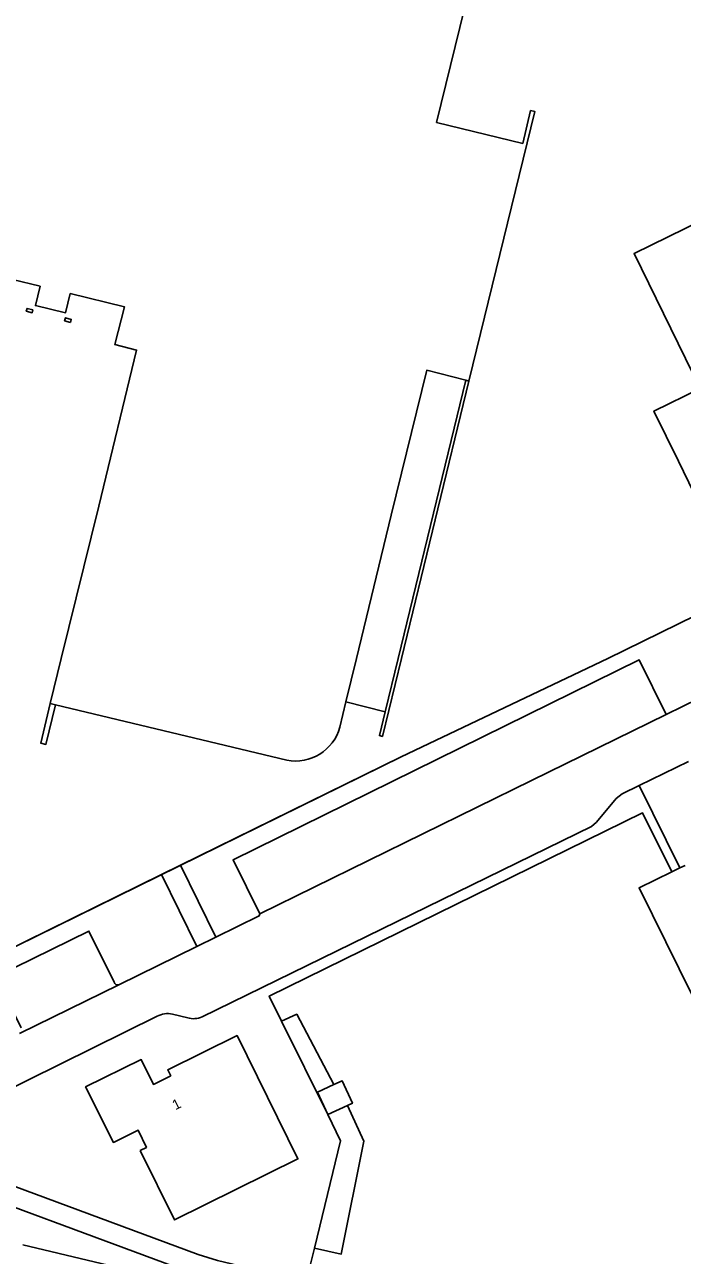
# Model space of a CAD drawing. Extents: x 163046 to 165074, y 382019 to 382874.
# Drawn here: x 163184.8 to 163250, y 382690.8 to 382812.9 of the extents above; entities that cross this region are included whole.
import ezdxf

# ---------------------------------------------------------------- set-up
doc = ezdxf.new("R2010")
doc.units = 0
for name, color, linetype in [('IMGEO_Fietspad_open', 7, 'Continuous'), ('IMGEO_Groenvoorziening', 7, 'Continuous'), ('IMGEO_Hek', 7, 'Continuous'), ('IMGEO_Muur', 7, 'Continuous'), ('IMGEO_Pand', 7, 'Continuous'), ('IMGEO_Pand_nummerreeks', 7, 'Continuous'), ('IMGEO_Parkeervlak_open', 7, 'Continuous'), ('IMGEO_Rijbaan_lokaal_gesloten', 7, 'Continuous'), ('IMGEO_Voetpad_open', 7, 'Continuous')]:
    doc.layers.add(name, color=color, linetype=linetype)

msp = doc.modelspace()

# ---------------------------------------------------------------- linework, layer by layer
at = {"layer": 'IMGEO_Fietspad_open'}
for points in [[(163172.35, 382701.93), (163176, 382700.52), (163201.96, 382690.91), (163203.88, 382690.32), (163252.46, 382678.73)], [(163252.01, 382676.83), (163203.95, 382688.31), (163202.36, 382688.7), (163201.62, 382688.96), (163172.54, 382699.75), (163171.68, 382699.94), (163168.8, 382700.21)]]:
    msp.add_lwpolyline(points, dxfattribs=at)
at = {"layer": 'IMGEO_Groenvoorziening'}
for points in [[(163200.21, 382729.51), (163222.08, 382740.26), (163242.58, 382750), (163320.84, 382788.38), (163326.4, 382790.68), (163329.21, 382791.76), (163334.82, 382793.72), (163337.67, 382794.6), (163343.5, 382795.94), (163349.43, 382797.09), (163352.45, 382797.4), (163359.37, 382797.83)], [(163163.24, 382720.72), (163175.88, 382717.55), (163198.33, 382728.59)]]:
    msp.add_lwpolyline(points, dxfattribs=at)
at = {"layer": 'IMGEO_Hek'}
for points in [[(163359.37, 382797.83), (163352.45, 382797.4), (163349.43, 382797.09), (163343.5, 382795.94), (163337.67, 382794.6), (163334.82, 382793.72), (163329.21, 382791.76), (163326.4, 382790.68), (163320.84, 382788.38), (163242.58, 382750), (163222.08, 382740.26)], [(163222.08, 382740.26), (163175.88, 382717.55), (163161.49, 382721.16)]]:
    msp.add_lwpolyline(points, dxfattribs=at)
at = {"layer": 'IMGEO_Muur'}
for points in [[(163228.81, 382777.5), (163222.11, 382750), (163220.23, 382742.28), (163219.93, 382742.36), (163220.5, 382744.72)], [(163220.5, 382744.72), (163221.79, 382750), (163228.51, 382777.59)], [(163187.82, 382745.42), (163186.87, 382741.49), (163186.35, 382741.62), (163187.29, 382745.55)]]:
    msp.add_lwpolyline(points, dxfattribs=at)
at = {"layer": 'IMGEO_Pand'}
for points in [[(163187.29, 382745.55), (163188.39, 382750), (163192.11, 382765.11), (163195.86, 382780.59), (163193.71, 382781.12), (163194.64, 382784.88), (163189.27, 382786.19), (163188.81, 382784.29), (163185.83, 382785), (163186.29, 382786.91), (163175.29, 382789.56), (163181.21, 382813.84), (163184.93, 382829.07), (163223.48, 382819.67), (163229.29, 382818.25), (163225.61, 382803.16), (163234.14, 382801.08), (163234.93, 382804.33), (163235.33, 382804.24), (163228.81, 382777.5)], [(163260.37, 382797.58), (163257.72, 382803.04), (163272.56, 382810.28), (163275.22, 382804.81), (163285.92, 382810.05), (163288.8, 382804.14), (163299.84, 382781.52), (163300.53, 382780.1), (163259.8, 382760.22), (163255.22, 382757.98), (163249.59, 382769.57), (163247.16, 382774.53), (163251.73, 382776.78), (163245.19, 382790.17), (163260.37, 382797.58)], [(163185.58, 382784.57), (163185.5, 382784.28), (163184.92, 382784.43), (163185, 382784.72), (163185.58, 382784.57)], [(163189.29, 382783.33), (163188.71, 382783.49), (163188.79, 382783.78), (163189.37, 382783.62), (163189.29, 382783.33)], [(163216.6, 382745.71), (163217.65, 382750), (163221.11, 382764.2), (163224.63, 382778.58), (163228.51, 382777.59)], [(163228.51, 382777.59), (163228.81, 382777.5)], [(163216.6, 382745.71), (163216.01, 382743.2)], [(163187.29, 382745.55), (163187.82, 382745.42)], [(163210.74, 382739.91), (163187.82, 382745.42)], [(163196.2, 382701.21), (163196.83, 382701.53), (163196.01, 382703.25), (163193.55, 382702.02), (163190.8, 382707.52), (163196.32, 382710.24), (163197.53, 382707.78), (163199.24, 382708.63), (163198.95, 382709.22), (163205.82, 382712.62), (163211.85, 382700.39), (163199.63, 382694.34), (163196.2, 382701.21)], [(163216.76, 382705.68), (163217.25, 382705.9), (163216.23, 382708.13), (163215.4, 382707.75)], [(163214.82, 382704.79), (163213.8, 382707.02), (163215.4, 382707.75)], [(163216.76, 382705.68), (163214.82, 382704.79)]]:
    msp.add_lwpolyline(points, dxfattribs=at)
msp.add_arc((163211.6, 382744.41), 4.58, 259.2784, 344.701, dxfattribs=at)
at = {"layer": 'IMGEO_Parkeervlak_open'}
for points in [[(163208.06, 382724.68), (163205.42, 382730.04), (163232.39, 382743.33), (163245.68, 382749.88), (163248.36, 382744.45)], [(163259.48, 382710.67), (163254.98, 382708.45), (163245.69, 382727.26), (163248.93, 382728.85)], [(163250.24, 382729.49), (163249.72, 382729.24)], [(163184.4, 382713.38), (163181.88, 382718.44), (163191.13, 382722.98), (163193.64, 382717.92)], [(163215.4, 382707.75), (163211.73, 382714.73), (163210.24, 382714.06)], [(163213.5, 382691.55), (163216.15, 382690.95), (163218.39, 382702.14), (163216.76, 382705.68)]]:
    msp.add_lwpolyline(points, dxfattribs=at)
msp.add_arc((163194, 382718.02), 0.379, 195.2459, 283.2376, dxfattribs=at)
at = {"layer": 'IMGEO_Rijbaan_lokaal_gesloten'}
for points in [[(163323, 382780.97), (163259.7, 382750), (163248.36, 382744.45)], [(163220.5, 382744.72), (163216.6, 382745.71)], [(163248.36, 382744.45), (163235.01, 382737.92), (163208.06, 382724.68)], [(163245.68, 382737.41), (163250.57, 382739.8)], [(163202.36, 382714.48), (163240.95, 382733.35), (163241.47, 382733.79), (163243.4, 382736.12), (163244.02, 382736.59), (163245.68, 382737.41)], [(163208.06, 382724.68), (163208.02, 382724.48), (163203.71, 382722.37)], [(163201.83, 382721.45), (163194.09, 382717.65)], [(163203.71, 382722.37), (163201.83, 382721.45)], [(163194.09, 382717.65), (163184.23, 382712.81)], [(163172.35, 382701.93), (163197.88, 382714.53)], [(163199.4, 382714.75), (163200.93, 382714.39)], [(163184.58, 382691.88), (163203.7, 382687.3), (163251.29, 382675.9)]]:
    msp.add_lwpolyline(points, dxfattribs=at)
for centre, radius, start, end in [((163198.95, 382712.61), 2.19, 77.9738, 119.014), ((163201.52, 382716.2), 1.91, 251.7554, 295.8303)]:
    msp.add_arc(centre, radius, start, end, dxfattribs=at)
at = {"layer": 'IMGEO_Voetpad_open'}
for points in [[(163249.72, 382729.24), (163245.68, 382737.41)], [(163210.24, 382714.06), (163209.01, 382716.54), (163246.01, 382734.71), (163248.93, 382728.85)], [(163198.33, 382728.59), (163200.21, 382729.51)], [(163200.21, 382729.51), (163203.71, 382722.37)], [(163248.93, 382728.85), (163249.72, 382729.24)], [(163201.83, 382721.45), (163198.33, 382728.59)], [(163210.24, 382714.06), (163214.82, 382704.79)], [(163214.82, 382704.79), (163216.09, 382702.18), (163213.5, 382691.55)], [(163252.81, 382680.18), (163213.05, 382689.7), (163213.5, 382691.55)]]:
    msp.add_lwpolyline(points, dxfattribs=at)

# ---------------------------------------------------------------- texts
at = {"layer": 'IMGEO_Pand_nummerreeks'}
msp.add_text('1', height=1, rotation=26.4309, dxfattribs=at).set_placement((163199.7, 382705.2))

doc.saveas('drawing.dxf')
